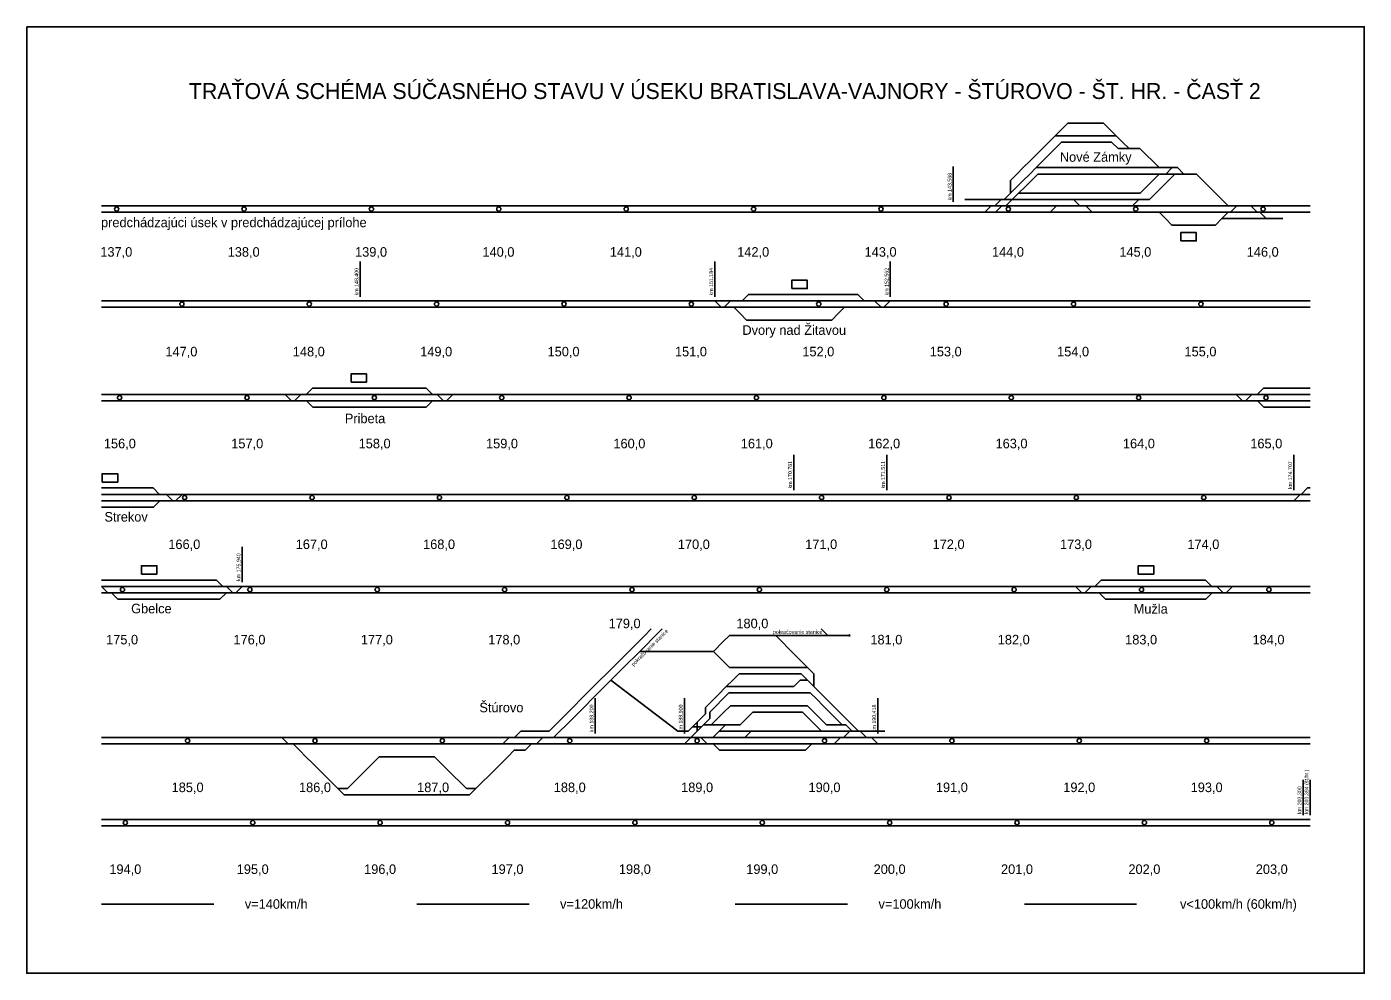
# Model space of a CAD drawing. Extents: x 44 to 1904, y 374 to 671.
# Drawn here: x 1172.7 to 1592.7, y 373.6 to 670.6 of the extents above; entities that cross this region are included whole.
import ezdxf

# ---------------------------------------------------------------- set-up
doc = ezdxf.new("R2010")
doc.units = 0
for name, color, linetype in [('2', 7, 'Continuous'), ('NAVRH', 7, 'Continuous'), ('Vrstva 1', 7, 'Continuous')]:
    doc.layers.add(name, color=color, linetype=linetype)

msp = doc.modelspace()

# ---------------------------------------------------------------- linework, layer by layer
at = {"layer": '2'}
for p, q in [((1499.59, 640.39), (1510.78, 640.39)), ((1495.59, 636.39), (1514.78, 636.39)), ((1513.33, 634.39), (1497.59, 634.39)), ((1522.22, 632.39), (1515.33, 632.39)), ((1528.22, 626.39), (1489.59, 626.39)), ((1533.96, 626.39), (1528.22, 626.39)), ((1481.59, 618.39), (1481.59, 622.39)), ((1528.29, 624.39), (1490.13, 624.39)), ((1533.21, 624.39), (1528.29, 624.39)), ((1539.96, 624.39), (1533.21, 624.39)), ((1522.29, 618.39), (1484.13, 618.39)), ((1196.13, 614.39), (1463.61, 614.39)), ((1463.61, 614.39), (1575.68, 614.39)), ((1521.85, 616.39), (1467.19, 616.39)), ((1521.85, 616.39), (1525.21, 616.39)), ((1196.13, 612.39), (1463.61, 612.39)), ((1463.61, 612.39), (1575.68, 612.39)), ((1547.89, 610.39), (1567.11, 610.39)), ((1532.21, 608.39), (1545.89, 608.39)), ((1196.13, 584.57), (1277.35, 584.57)), ((1277.35, 584.57), (1388.71, 584.57)), ((1388.71, 584.57), (1443.83, 584.57)), ((1399.31, 586.57), (1433.66, 586.57)), ((1443.83, 584.57), (1575.68, 584.57)), ((1196.13, 582.57), (1277.35, 582.57)), ((1277.35, 582.57), (1388.71, 582.57)), ((1388.71, 582.57), (1443.83, 582.57)), ((1443.83, 582.57), (1575.68, 582.57)), ((1398.71, 578.57), (1425.47, 578.57)), ((1196.13, 555.22), (1575.68, 555.22)), ((1262.37, 557.22), (1298.08, 557.22)), ((1561.01, 557.22), (1575.68, 557.22)), ((1196.13, 553.22), (1575.68, 553.22)), ((1262.52, 551.22), (1298.06, 551.22)), ((1561.16, 551.22), (1575.68, 551.22)), ((1212.38, 525.87), (1196.13, 525.87)), ((1574.85, 525.87), (1575.68, 525.87)), ((1196.13, 523.87), (1413.49, 523.87)), ((1196.13, 521.87), (1413.49, 521.87)), ((1413.49, 523.87), (1442.69, 523.87)), ((1413.49, 521.87), (1442.69, 521.87)), ((1442.69, 523.87), (1570.53, 523.87)), ((1442.69, 521.87), (1570.53, 521.87)), ((1570.53, 523.87), (1575.68, 523.87)), ((1570.53, 521.87), (1575.68, 521.87)), ((1212.42, 519.87), (1196.13, 519.87)), ((1232.23, 496.99), (1196.13, 496.99)), ((1510.02, 496.99), (1542.83, 496.99)), ((1196.13, 494.99), (1240.31, 494.99)), ((1196.13, 492.99), (1240.31, 492.99)), ((1240.31, 494.99), (1575.68, 494.99)), ((1240.31, 492.99), (1575.68, 492.99)), ((1233.33, 490.99), (1201.26, 490.99)), ((1511.41, 490.99), (1542.89, 490.99)), ((1407.83, 479.55), (1393.28, 479.55)), ((1407.83, 479.55), (1431.03, 479.55)), ((1388.32, 474.59), (1365.13, 474.59)), ((1417.83, 469.55), (1393.36, 469.55)), ((1415.83, 467.55), (1396.33, 467.55)), ((1419.83, 463.55), (1419.83, 467.55)), ((1377.12, 449.55), (1356.09, 465.55)), ((1413.53, 463.55), (1392.33, 463.55)), ((1417.83, 465.55), (1415.53, 465.55)), ((1393.16, 461.55), (1418.71, 461.55)), ((1385.75, 454.96), (1385.75, 456.96)), ((1387.16, 453.55), (1387.16, 455.55)), ((1417.77, 457.55), (1393.59, 457.55)), ((1400.63, 455.55), (1416.2, 455.55)), ((1327.78, 449.55), (1336.66, 449.55)), ((1377.12, 449.55), (1380.33, 449.55)), ((1392.07, 451.55), (1385.16, 451.55)), ((1442.07, 449.55), (1390.07, 449.55)), ((1396.63, 451.55), (1392.07, 451.55)), ((1429.83, 451.55), (1423.77, 451.55)), ((1196.13, 447.55), (1351.16, 447.55)), ((1196.13, 445.55), (1351.16, 445.55)), ((1351.16, 447.55), (1379.16, 447.55)), ((1351.16, 445.55), (1379.16, 445.55)), ((1379.16, 447.55), (1439.88, 447.55)), ((1379.16, 445.55), (1439.88, 445.55)), ((1439.88, 447.55), (1575.68, 447.55)), ((1439.88, 445.55), (1575.68, 445.55)), ((1300.71, 441.55), (1283.33, 441.55)), ((1329.15, 443.55), (1325.71, 443.55)), ((1390.16, 443.55), (1417.23, 443.55)), ((1270.33, 431.55), (1273.33, 431.55)), ((1272.33, 429.55), (1311.71, 429.55)), ((1313.71, 431.55), (1310.71, 431.55)), ((1196.13, 421.87), (1574.57, 421.87)), ((1574.57, 421.87), (1575.68, 421.87)), ((1196.13, 419.87), (1574.57, 419.87)), ((1574.57, 419.87), (1575.68, 419.87))]:
    msp.add_line(p, q, dxfattribs=at)
msp.add_lwpolyline([(1431.03, 479.55), (1431.03, 479.89), (1431.03, 479.23)], dxfattribs=at)
at = {"layer": 'NAVRH'}
for p, q in [((1497.59, 638.39), (1499.59, 640.39)), ((1512.78, 638.39), (1510.78, 640.39)), ((1491.59, 632.39), (1493.59, 634.39)), ((1493.59, 634.39), (1495.59, 636.39)), ((1495.59, 636.39), (1497.59, 638.39)), ((1495.59, 632.39), (1497.59, 634.39)), ((1514.78, 636.39), (1512.78, 638.39)), ((1515.33, 632.39), (1513.33, 634.39)), ((1516.78, 634.39), (1514.78, 636.39)), ((1518.78, 632.39), (1516.78, 634.39)), ((1487.59, 628.39), (1489.59, 630.39)), ((1489.59, 630.39), (1491.59, 632.39)), ((1491.59, 628.39), (1493.59, 630.39)), ((1493.59, 630.39), (1495.59, 632.39)), ((1524.22, 630.39), (1522.22, 632.39)), ((1526.22, 628.39), (1524.22, 630.39)), ((1483.59, 624.39), (1485.59, 626.39)), ((1485.59, 626.39), (1487.59, 628.39)), ((1485.59, 626.39), (1487.59, 628.39)), ((1487.59, 624.39), (1489.59, 626.39)), ((1489.59, 626.39), (1491.59, 628.39)), ((1528.22, 626.39), (1526.22, 628.39)), ((1530.33, 624.39), (1532.33, 626.39)), ((1535.96, 624.39), (1533.96, 626.39)), ((1481.59, 622.39), (1483.59, 624.39)), ((1483.59, 620.39), (1485.59, 622.39)), ((1485.59, 622.39), (1487.59, 624.39)), ((1486.13, 620.39), (1488.13, 622.39)), ((1488.13, 622.39), (1490.13, 624.39)), ((1524.29, 620.39), (1526.29, 622.39)), ((1526.29, 622.39), (1528.29, 624.39)), ((1529.21, 620.39), (1531.21, 622.39)), ((1531.21, 622.39), (1533.21, 624.39)), ((1541.96, 622.39), (1539.96, 624.39)), ((1543.96, 620.39), (1541.96, 622.39)), ((1479.59, 616.39), (1481.59, 618.39)), ((1481.59, 618.39), (1483.59, 620.39)), ((1482.13, 616.39), (1484.13, 618.39)), ((1484.13, 618.39), (1486.13, 620.39)), ((1522.29, 618.39), (1524.29, 620.39)), ((1525.21, 616.39), (1527.21, 618.39)), ((1527.21, 618.39), (1529.21, 620.39)), ((1545.96, 618.39), (1543.96, 620.39)), ((1547.96, 616.39), (1545.96, 618.39)), ((1473.53, 612.39), (1475.53, 614.39)), ((1476.61, 614.39), (1478.61, 616.39)), ((1476.89, 612.39), (1478.89, 614.39)), ((1480.13, 614.39), (1482.13, 616.39)), ((1494.05, 612.39), (1496.05, 614.39)), ((1503.37, 614.39), (1501.37, 616.39)), ((1507.21, 612.39), (1505.21, 614.39)), ((1519.85, 614.39), (1521.85, 616.39)), ((1549.96, 614.39), (1547.96, 616.39)), ((1550.65, 612.39), (1552.65, 614.39)), ((1559.01, 612.39), (1557.01, 614.39)), ((1530.21, 610.39), (1528.21, 612.39)), ((1532.21, 608.39), (1530.21, 610.39)), ((1545.89, 608.39), (1547.89, 610.39)), ((1547.89, 610.39), (1549.89, 612.39)), ((1561.81, 610.39), (1559.81, 612.39)), ((1390.71, 582.57), (1388.71, 584.57)), ((1391.62, 582.57), (1393.62, 584.57)), ((1397.31, 584.57), (1399.31, 586.57)), ((1435.66, 584.57), (1433.66, 586.57)), ((1440.91, 582.57), (1438.91, 584.57)), ((1441.83, 582.57), (1443.83, 584.57)), ((1396.71, 580.57), (1394.71, 582.57)), ((1398.71, 578.57), (1396.71, 580.57)), ((1425.47, 578.57), (1427.47, 580.57)), ((1427.47, 580.57), (1429.47, 582.57)), ((1255.8, 553.22), (1253.8, 555.22)), ((1256.71, 553.22), (1258.71, 555.22)), ((1260.37, 555.22), (1262.37, 557.22)), ((1300.08, 555.22), (1298.08, 557.22)), ((1303.53, 553.22), (1301.53, 555.22)), ((1304.44, 553.22), (1306.44, 555.22)), ((1554.44, 553.22), (1552.44, 555.22)), ((1555.35, 553.22), (1557.35, 555.22)), ((1559.01, 555.22), (1561.01, 557.22)), ((1262.52, 551.22), (1260.52, 553.22)), ((1298.06, 551.22), (1300.06, 553.22)), ((1561.16, 551.22), (1559.16, 553.22)), ((1214.38, 523.87), (1212.38, 525.87)), ((1572.85, 523.87), (1574.85, 525.87)), ((1212.42, 519.87), (1214.42, 521.87)), ((1218.5, 521.87), (1216.5, 523.87)), ((1219.41, 521.87), (1221.41, 523.87)), ((1570.53, 521.87), (1572.53, 523.87)), ((1234.23, 494.99), (1232.23, 496.99)), ((1508.02, 494.99), (1510.02, 496.99)), ((1544.83, 494.99), (1542.83, 496.99)), ((1198.13, 492.99), (1196.13, 494.99)), ((1201.26, 490.99), (1199.26, 492.99)), ((1233.33, 490.99), (1235.33, 492.99)), ((1237.39, 492.99), (1235.39, 494.99)), ((1238.31, 492.99), (1240.31, 494.99)), ((1503.95, 492.99), (1501.95, 494.99)), ((1504.86, 492.99), (1506.86, 494.99)), ((1511.41, 490.99), (1509.41, 492.99)), ((1542.89, 490.99), (1544.89, 492.99)), ((1548.39, 492.99), (1546.39, 494.99)), ((1549.31, 492.99), (1551.31, 494.99)), ((1361.69, 474.59), (1366.73, 479.62)), ((1366.73, 479.62), (1368.73, 481.62)), ((1369.13, 478.59), (1372.17, 481.62)), ((1391.28, 477.55), (1393.28, 479.55)), ((1409.83, 477.55), (1407.83, 479.55)), ((1424.23, 479.55), (1422.16, 481.62)), ((1365.13, 474.59), (1367.13, 476.59)), ((1367.13, 476.59), (1369.13, 478.59)), ((1388.32, 474.59), (1391.28, 477.55)), ((1411.83, 475.55), (1409.83, 477.55)), ((1413.83, 473.55), (1411.83, 475.55)), ((1356.66, 469.55), (1361.69, 474.59)), ((1360.09, 469.55), (1365.13, 474.59)), ((1391.36, 471.55), (1388.32, 474.59)), ((1393.36, 469.55), (1391.36, 471.55)), ((1415.83, 471.55), (1413.83, 473.55)), ((1417.83, 469.55), (1415.83, 471.55)), ((1352.66, 465.55), (1354.66, 467.55)), ((1354.66, 467.55), (1356.66, 469.55)), ((1356.09, 465.55), (1358.09, 467.55)), ((1358.09, 467.55), (1360.09, 469.55)), ((1394.33, 465.55), (1396.33, 467.55)), ((1417.83, 465.55), (1415.83, 467.55)), ((1419.83, 467.55), (1417.83, 469.55)), ((1348.66, 461.55), (1350.66, 463.55)), ((1350.66, 463.55), (1352.66, 465.55)), ((1352.09, 461.55), (1354.09, 463.55)), ((1354.09, 463.55), (1356.09, 465.55)), ((1389.75, 460.96), (1392.33, 463.55)), ((1392.33, 463.55), (1394.33, 465.55)), ((1413.53, 463.55), (1415.53, 465.55)), ((1419.83, 463.55), (1417.83, 465.55)), ((1421.83, 461.55), (1419.83, 463.55)), ((1344.66, 457.55), (1346.66, 459.55)), ((1346.66, 459.55), (1348.66, 461.55)), ((1348.09, 457.55), (1350.09, 459.55)), ((1350.09, 459.55), (1352.09, 461.55)), ((1385.75, 456.96), (1387.75, 458.96)), ((1387.75, 458.96), (1389.75, 460.96)), ((1389.16, 457.55), (1391.16, 459.55)), ((1391.16, 459.55), (1393.16, 461.55)), ((1420.71, 459.55), (1418.71, 461.55)), ((1422.71, 457.55), (1420.71, 459.55)), ((1423.83, 459.55), (1421.83, 461.55)), ((1425.83, 457.55), (1423.83, 459.55)), ((1340.66, 453.55), (1342.66, 455.55)), ((1342.66, 455.55), (1344.66, 457.55)), ((1344.09, 453.55), (1346.09, 455.55)), ((1346.09, 455.55), (1348.09, 457.55)), ((1383.75, 452.96), (1385.75, 454.96)), ((1387.16, 455.55), (1389.16, 457.55)), ((1389.59, 453.55), (1391.59, 455.55)), ((1391.59, 455.55), (1393.59, 457.55)), ((1398.63, 453.55), (1400.63, 455.55)), ((1418.2, 453.55), (1416.2, 455.55)), ((1419.77, 455.55), (1417.77, 457.55)), ((1421.77, 453.55), (1419.77, 455.55)), ((1424.71, 455.55), (1422.71, 457.55)), ((1426.71, 453.55), (1424.71, 455.55)), ((1427.83, 455.55), (1425.83, 457.55)), ((1429.83, 453.55), (1427.83, 455.55)), ((1325.78, 447.55), (1327.78, 449.55)), ((1336.66, 449.55), (1338.66, 451.55)), ((1338.09, 447.55), (1340.09, 449.55)), ((1338.66, 451.55), (1340.66, 453.55)), ((1340.09, 449.55), (1342.09, 451.55)), ((1342.09, 451.55), (1344.09, 453.55)), ((1380.33, 449.55), (1381.75, 450.96)), ((1381.16, 447.55), (1383.16, 449.55)), ((1381.75, 450.96), (1383.75, 452.96)), ((1384.58, 450.96), (1381.75, 450.96)), ((1383.16, 449.55), (1383.16, 452.38)), ((1383.16, 449.55), (1385.16, 451.55)), ((1385.16, 451.55), (1387.16, 453.55)), ((1387.59, 451.55), (1389.59, 453.55)), ((1388.07, 447.55), (1390.07, 449.55)), ((1390.07, 449.55), (1392.07, 451.55)), ((1396.63, 451.55), (1398.63, 453.55)), ((1398.16, 447.55), (1400.16, 449.55)), ((1420.2, 451.55), (1418.2, 453.55)), ((1422.2, 449.55), (1420.2, 451.55)), ((1423.77, 451.55), (1421.77, 453.55)), ((1428.71, 451.55), (1426.71, 453.55)), ((1429.1, 447.55), (1431.1, 449.55)), ((1431.83, 451.55), (1429.83, 453.55)), ((1431.83, 449.55), (1429.83, 451.55)), ((1433.83, 449.55), (1431.83, 451.55)), ((1436.39, 447.55), (1434.39, 449.55)), ((1254.76, 445.55), (1252.76, 447.55)), ((1258.33, 443.55), (1256.33, 445.55)), ((1322.16, 445.55), (1324.16, 447.55)), ((1329.15, 443.55), (1331.15, 445.55)), ((1332.73, 445.55), (1334.73, 447.55)), ((1379.16, 445.55), (1381.16, 447.55)), ((1386.3, 445.55), (1384.3, 447.55)), ((1390.16, 443.55), (1388.16, 445.55)), ((1417.23, 443.55), (1419.23, 445.55)), ((1426.21, 445.55), (1428.21, 447.55)), ((1439.88, 445.55), (1437.88, 447.55)), ((1260.33, 441.55), (1258.33, 443.55)), ((1262.33, 439.55), (1260.33, 441.55)), ((1281.33, 439.55), (1283.33, 441.55)), ((1302.71, 439.55), (1300.71, 441.55)), ((1321.71, 439.55), (1323.71, 441.55)), ((1323.71, 441.55), (1325.71, 443.55)), ((1264.33, 437.55), (1262.33, 439.55)), ((1266.33, 435.55), (1264.33, 437.55)), ((1277.33, 435.55), (1279.33, 437.55)), ((1279.33, 437.55), (1281.33, 439.55)), ((1304.71, 437.55), (1302.71, 439.55)), ((1306.71, 435.55), (1304.71, 437.55)), ((1317.71, 435.55), (1319.71, 437.55)), ((1319.71, 437.55), (1321.71, 439.55)), ((1268.33, 433.55), (1266.33, 435.55)), ((1270.33, 431.55), (1268.33, 433.55)), ((1273.33, 431.55), (1275.33, 433.55)), ((1275.33, 433.55), (1277.33, 435.55)), ((1308.71, 433.55), (1306.71, 435.55)), ((1310.71, 431.55), (1308.71, 433.55)), ((1313.71, 431.55), (1315.71, 433.55)), ((1315.71, 433.55), (1317.71, 435.55)), ((1272.33, 429.55), (1270.33, 431.55)), ((1311.71, 429.55), (1313.71, 431.55))]:
    msp.add_line(p, q, dxfattribs=at)
for points in [[(1535.03, 603.39), (1539.92, 603.39), (1539.92, 605.99), (1535.03, 605.99)], [(1412.85, 588.43), (1417.74, 588.43), (1417.74, 591.03), (1412.85, 591.03)], [(1274.5, 559.08), (1279.39, 559.08), (1279.39, 561.68), (1274.5, 561.68)], [(1196.33, 527.73), (1201.23, 527.73), (1201.23, 530.33), (1196.33, 530.33)], [(1208.65, 498.85), (1213.54, 498.85), (1213.54, 501.45), (1208.65, 501.45)], [(1521.66, 498.85), (1526.56, 498.85), (1526.56, 501.45), (1521.66, 501.45)]]:
    msp.add_lwpolyline(points, close=True, dxfattribs=at)
for centre in [(1200.89, 613.39), (1240.89, 613.39), (1280.89, 613.39), (1320.89, 613.39), (1360.89, 613.39), (1400.89, 613.39), (1440.89, 613.39), (1480.89, 613.39), (1520.89, 613.39), (1560.89, 613.39), (1221.35, 583.57), (1261.35, 583.57), (1301.35, 583.57), (1341.35, 583.57), (1381.35, 583.57), (1421.35, 583.57), (1461.35, 583.57), (1501.35, 583.57), (1541.35, 583.57), (1201.8, 554.22), (1241.8, 554.22), (1281.8, 554.22), (1321.8, 554.22), (1361.8, 554.22), (1401.8, 554.22), (1441.8, 554.22), (1481.8, 554.22), (1521.8, 554.22), (1561.8, 554.22), (1222.25, 522.87), (1262.25, 522.87), (1302.25, 522.87), (1342.25, 522.87), (1382.25, 522.87), (1422.25, 522.87), (1462.25, 522.87), (1502.25, 522.87), (1542.25, 522.87), (1202.71, 493.99), (1242.71, 493.99), (1282.71, 493.99), (1322.71, 493.99), (1362.71, 493.99), (1402.71, 493.99), (1442.71, 493.99), (1482.71, 493.99), (1522.71, 493.99), (1562.71, 493.99), (1223.16, 446.55), (1263.16, 446.55), (1303.16, 446.55), (1343.16, 446.55), (1383.16, 446.55), (1423.16, 446.55), (1463.16, 446.55), (1503.16, 446.55), (1543.16, 446.55), (1203.62, 420.87), (1203.62, 420.87), (1243.62, 420.87), (1283.62, 420.87), (1323.62, 420.87), (1363.62, 420.87), (1403.62, 420.87), (1443.62, 420.87), (1483.62, 420.87), (1523.62, 420.87), (1563.62, 420.87)]:
    msp.add_circle(centre, 0.666, dxfattribs=at)
at = {"layer": 'Vrstva 1'}
for p, q in [((1172.65, 670.6), (1172.65, 373.6)), ((1382.65, 670.6), (1172.65, 670.6)), ((1382.65, 670.6), (1592.65, 670.6)), ((1592.65, 373.6), (1592.65, 670.6)), ((1463.61, 615.71), (1463.61, 626.79)), ((1277.35, 585.88), (1277.35, 596.97)), ((1388.71, 585.88), (1388.71, 596.97)), ((1443.83, 585.88), (1443.83, 596.97)), ((1413.49, 525.18), (1413.49, 536.27)), ((1442.69, 525.18), (1442.69, 536.27)), ((1570.53, 525.18), (1570.53, 536.27)), ((1240.31, 496.31), (1240.31, 507.39)), ((1351.16, 448.87), (1351.16, 459.95)), ((1379.16, 448.87), (1379.16, 459.95)), ((1439.88, 448.87), (1439.88, 459.95)), ((1573.47, 423.19), (1573.47, 434.27)), ((1575.68, 423.19), (1575.68, 434.27)), ((1231.38, 395.32), (1196.13, 395.32)), ((1330.39, 395.32), (1295.14, 395.32)), ((1430.38, 395.32), (1395.13, 395.32)), ((1521.17, 395.32), (1485.92, 395.32)), ((1172.65, 373.6), (1382.65, 373.6)), ((1382.65, 373.6), (1592.65, 373.6))]:
    msp.add_line(p, q, dxfattribs=at)
msp.add_lwpolyline([(1172.65, 670.6), (1592.65, 670.6), (1592.65, 373.6), (1172.65, 373.6)], close=True, dxfattribs=at)

# ---------------------------------------------------------------- texts
at = {"layer": 'NAVRH'}
for s, height, p in [('TRAŤOVÁ SCHÉMA SÚČASNÉHO STAVU V ÚSEKU BRATISLAVA-VAJNORY - ŠTÚROVO - ŠT. HR. - ČASŤ 2', 5, (1223.57, 647.93)), ('Štúrovo', 3, (1314.79, 455.48)), ('v<100km/h (60km/h)', 3, (1534.8, 393.82))]:
    msp.add_text(s, height=height, dxfattribs=at).set_placement(p)
for s, p in [('Nové Zámky', (1497.07, 628.24)), ('predchádzajúci úsek v predchádzajúcej prílohe', (1195.97, 607.7)), ('137,0', (1195.75, 598.44)), ('138,0', (1235.75, 598.44)), ('139,0', (1275.75, 598.44)), ('140,0', (1315.75, 598.44)), ('141,0', (1355.75, 598.44)), ('142,0', (1395.75, 598.44)), ('143,0', (1435.75, 598.44)), ('144,0', (1475.75, 598.44)), ('145,0', (1515.75, 598.44)), ('146,0', (1555.75, 598.44)), ('Dvory nad Žitavou', (1397.38, 573.92)), ('147,0', (1216.2, 567.17)), ('148,0', (1256.2, 567.17)), ('149,0', (1296.2, 567.17)), ('150,0', (1336.2, 567.17)), ('151,0', (1376.2, 567.17)), ('152,0', (1416.2, 567.17)), ('153,0', (1456.2, 567.17)), ('154,0', (1496.2, 567.17)), ('155,0', (1536.2, 567.17)), ('Pribeta', (1272.53, 546.19)), ('156,0', (1196.87, 538.32)), ('157,0', (1236.87, 538.32)), ('158,0', (1276.87, 538.32)), ('159,0', (1316.87, 538.32)), ('160,0', (1356.87, 538.32)), ('161,0', (1396.87, 538.32)), ('162,0', (1436.87, 538.32)), ('163,0', (1476.87, 538.32)), ('164,0', (1516.87, 538.32)), ('165,0', (1556.87, 538.32)), ('Strekov', (1197.05, 515.32)), ('166,0', (1217.11, 506.7)), ('167,0', (1257.11, 506.7)), ('168,0', (1297.11, 506.7)), ('169,0', (1337.11, 506.7)), ('170,0', (1377.11, 506.7)), ('171,0', (1417.11, 506.7)), ('172,0', (1457.11, 506.7)), ('173,0', (1497.11, 506.7)), ('174,0', (1537.11, 506.7)), ('Gbelce', (1205.43, 486.53)), ('Mužla', (1520.25, 486.44)), ('179,0', (1355.37, 481.86)), ('180,0', (1395.49, 481.86)), ('175,0', (1197.57, 476.78)), ('176,0', (1237.57, 476.78)), ('177,0', (1277.57, 476.78)), ('178,0', (1317.57, 476.78)), ('181,0', (1437.57, 476.78)), ('182,0', (1477.57, 476.78)), ('183,0', (1517.57, 476.78)), ('184,0', (1557.57, 476.78)), ('185,0', (1218.14, 430.43)), ('186,0', (1258.14, 430.43)), ('187,0', (1295.24, 430.43)), ('188,0', (1338.14, 430.43)), ('189,0', (1378.14, 430.43)), ('190,0', (1418.14, 430.43)), ('191,0', (1458.14, 430.43)), ('192,0', (1498.14, 430.43)), ('193,0', (1538.14, 430.43)), ('194,0', (1198.59, 404.75)), ('195,0', (1238.59, 404.75)), ('196,0', (1278.59, 404.75)), ('197,0', (1318.59, 404.75)), ('198,0', (1358.59, 404.75)), ('199,0', (1398.59, 404.75)), ('200,0', (1438.59, 404.75)), ('201,0', (1478.59, 404.75)), ('202,0', (1518.59, 404.75)), ('203,0', (1558.59, 404.75)), ('v=140km/h', (1241.12, 393.82)), ('v=120km/h', (1340.13, 393.82)), ('v=100km/h', (1440.12, 393.82))]:
    msp.add_text(s, height=3, rotation=360, dxfattribs=at).set_placement(p)
at = {"layer": 'Vrstva 1'}
for s, rotation, p in [('km 143,568', 90, (1463.06, 616.1)), ('km 148,400', 90, (1276.79, 586.28)), ('km 151,184', 90, (1388.15, 586.28)), ('km 152,562', 90, (1443.27, 586.29)), ('km 170,781', 90, (1412.94, 525.7)), ('km 171,511', 90, (1442.14, 525.7)), ('km 174,707', 90, (1569.98, 525.58)), ('km 175,940', 90, (1239.76, 496.71)), ('pokračovanie stanice', 45, (1363.19, 469.86)), ('pokračovanie stanice', 360, (1406.95, 480.1)), ('km 188,200', 90, (1350.61, 449.26)), ('km 188,900', 90, (1378.61, 449.26)), ('km 190,418', 90, (1439.33, 449.26)), ('km 203,394 (št.hr.)', 90, (1575.12, 423.58)), ('km 203,300', 90, (1572.92, 423.59))]:
    msp.add_text(s, height=1.2, rotation=rotation, dxfattribs=at).set_placement(p)

doc.saveas('drawing.dxf')
